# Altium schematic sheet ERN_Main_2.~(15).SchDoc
size A; SheetNumber: 2; SheetTotal: 3; SPICEModelCacheYVUKJMZF: <root> / <DocumentId>YVUKJMZF</DocumentId> / <CacheFrame Number="0"> / <Model Name="1n5400" Kind="MDL"> / <Text>*1N5400 MCE / * 50V 3A Si Rectifier pkg:DO-201 1,2 / .MODEL 1N5400 D(IS=2.68E-12 RS=0.00977 N=1.17 TT=1.44E-5 CJO=1.24E-10 / + VJ=0.6 M=0.333 BV=66.6 IBV=1E-5 )</Text> / </Model> / <Model Name="led2" Kind="MDL"> / <Text>*Typ RED,GREEN,YELLOW,AMBER GaAs LED: Vf=2.1V Vr=4V If=40mA trr=3uS / *LED Pinout: 1=A, 2=K / .MODEL LED2 D (IS=93.1P RS=42M N=4.61 BV=4 IBV=10U / + CJO=2.97P VJ=.75 M=.333 TT=4.32U)</Text> / </Model> / </CacheFrame> / </root>
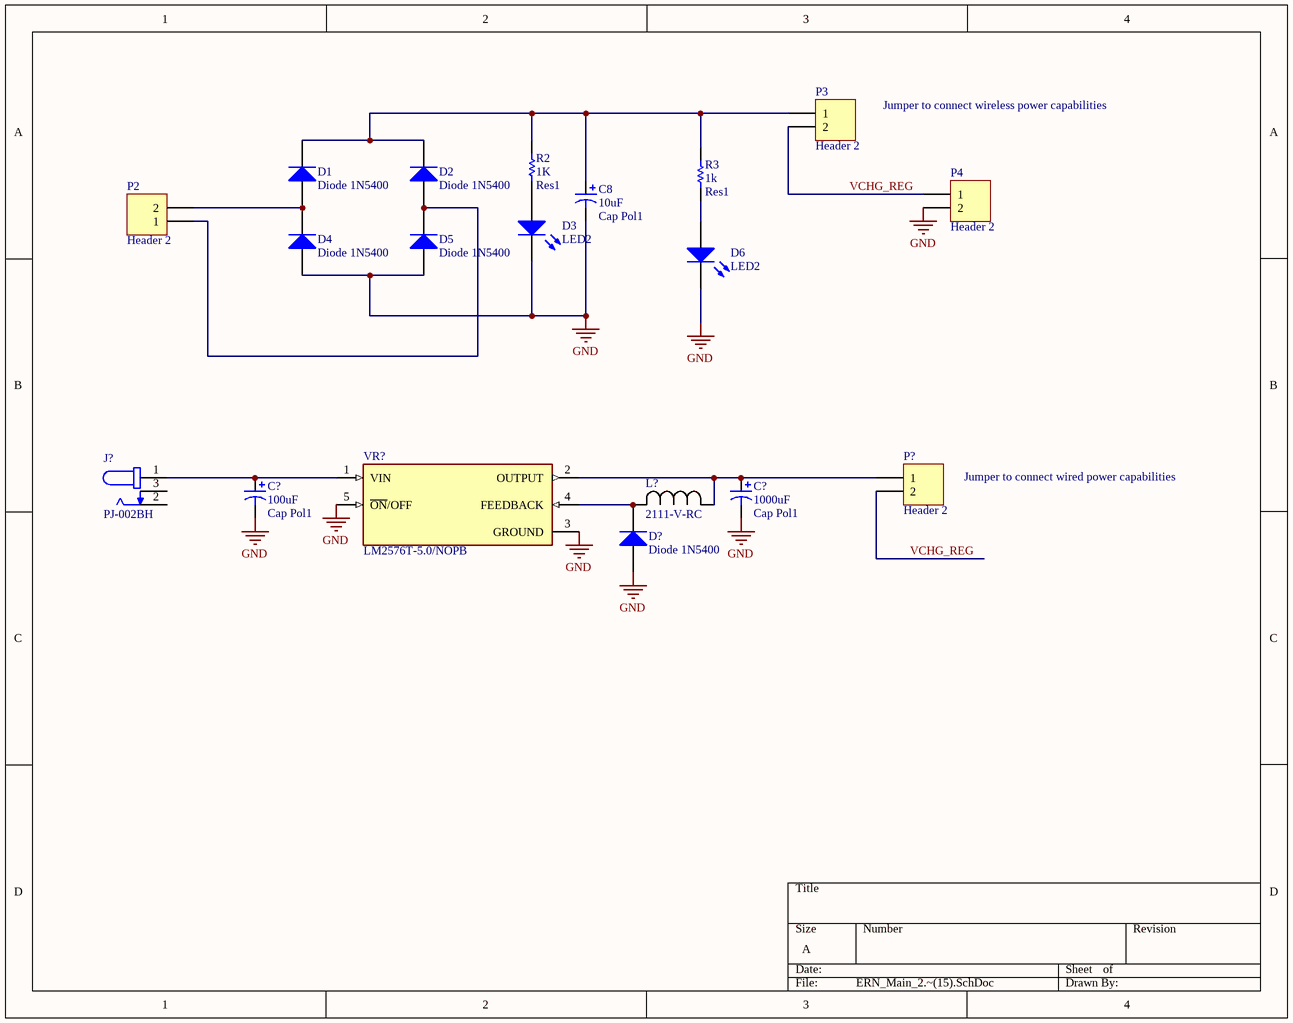
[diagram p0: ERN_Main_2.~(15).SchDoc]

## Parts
(Parts that share a designator on the sheet are numbered #1, #2 ... from top to bottom, then left to right.)
C8  Cap Pol1  value 10uF  [RB7.6-15]
C?#1  Cap Pol1  value 100uF  [RB7.6-15]
C?#2  Cap Pol1  value 1000uF  [RB7.6-15]
D1  Diode 1N5400  [DO-201AD]
D2  Diode 1N5400  [DO-201AD]
D3  LED2  [3.2X1.6X1.1]
D4  Diode 1N5400  [DO-201AD]
D5  Diode 1N5400  [DO-201AD]
D6  LED2  [3.2X1.6X1.1]
D?  Diode 1N5400  [DO-201AD]
J?  PJ-002BH  [CUI_PJ-002BH]
L?  2111-V-RC  [IND_21XX_27A_V]
P2  Header 2  [HDR1X2]
P3  Header 2  [HDR1X2]
P4  Header 2  [HDR1X2]
P?  Header 2  [HDR1X2]
R2  Res1  value 1K  [AXIAL-0.3]
R3  Res1  value 1k  [AXIAL-0.3]
VR?  LM2576T-5.0/NOPB  [TO170P1067X483X1651-5]

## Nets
GND: C8.2 C?#1.2 C?#2.2 D3.2(K) D4.1(A) D5.1(A) D6.2(K) D?.1(A) P4.2 VR?.3(GROUND) VR?.5(~{ON}/OFF)
VCHG_REG: P3.2 P4.1 P?.2
NetC8_1: C8.1 D1.2(K) D2.2(K) P3.1 R2.2 R3.2
NetC?#1_1: C?#1.1 J?.1 VR?.1(VIN)
NetC?#2_1: C?#2.1 L?.1 P?.1 VR?.2(OUTPUT)
NetD1_1: D1.1(A) D4.2(K) P2.2
NetD2_1: D2.1(A) D5.2(K) P2.1
NetD3_1: D3.1(A) R2.1
NetD6_1: D6.1(A) R3.1
NetD?_2: D?.2(K) L?.2 VR?.4(FEEDBACK)

Not connected (* = marked no-connect by the designer): J? 2 3

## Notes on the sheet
- Jumper to connect wireless power capabilities
- Jumper to connect wired power capabilities

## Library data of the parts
C8 C?#1 C?#2 = Cap Pol1: Polarized Capacitor (Radial)
D1 D2 D4 D5 D? = Diode 1N5400: 3 Amp General Purpose Rectifier
D3 D6 = LED2: Typical RED, GREEN, YELLOW, AMBER GaAs LED
J? = PJ-002BH: 2.5 x 6.5 mm, 5.0 A, Horizontal, Through Hole, Dc Power Jack Connector; MF: Same Sky
L? = 2111-V-RC: Inductor 68uH; Manufacturer_Name: Bourns Electronics
P2-P4 P? = Header 2: Header, 2-Pin
R2 R3 = Res1: Resistor
VR? = LM2576T-5.0/NOPB: SIMPLE SWITCHERÂ® 40V, 3A Low Component Count Step-Down Regulator; MF: Texas Instruments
